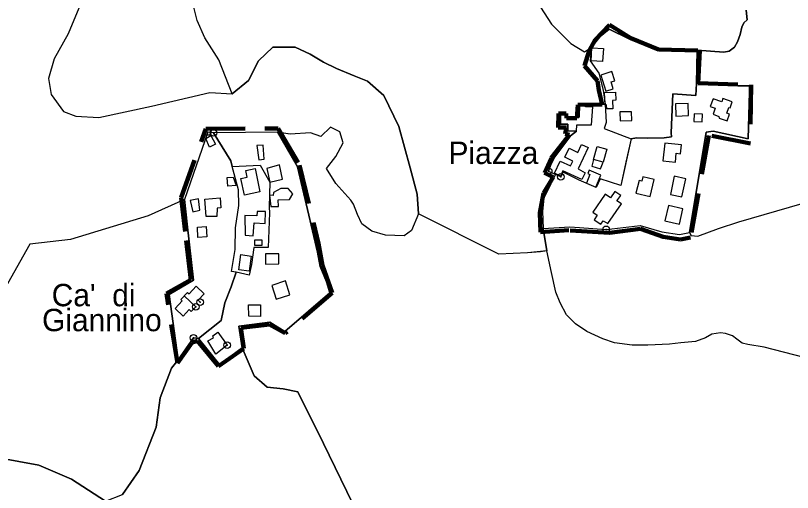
# Model space of a CAD drawing. Extents: x 645880 to 658994, y 884400 to 894744.
# Drawn here: x 655242 to 655833, y 890454 to 890817 of the extents above; entities that cross this region are included whole.
import ezdxf
from ezdxf.enums import TextEntityAlignment as Align

# ---------------------------------------------------------------- set-up
doc = ezdxf.new("R2010")
doc.units = 0
doc.header["$LTSCALE"] = 10
doc.header["$PDMODE"] = 32
doc.header["$PDSIZE"] = 5
doc.linetypes.add('MEDIUM_DASHED', pattern=[4.5, 3, -1.5])
for name, color, linetype, lineweight in [('1', 7, 'Continuous', 25), ('15', 7, 'MEDIUM_DASHED', 100), ('16', 7, 'Continuous', 25), ('17', 7, 'Continuous', 25), ('18', 7, 'Continuous', 25), ('6', 7, 'Continuous', 25), ('7', 7, 'Continuous', 25), ('8', 7, 'Continuous', 25)]:
    doc.layers.add(name, color=color, linetype=linetype, lineweight=lineweight)
doc.layers.add('60', color=7, linetype='Continuous')

msp = doc.modelspace()

# ---------------------------------------------------------------- linework, layer by layer
at = {"layer": '1'}
msp.add_line((655647.79, 890698.77), (655649.57, 890703.78), dxfattribs=at)
for points in [[(655649.57, 890703.78), (655652.57, 890709.54), (655664.32, 890725.65), (655668.89, 890729.13), (655662.28, 890729.46), (655662.45, 890734.52), (655656.71, 890734.52), (655656.76, 890743.16), (655660.15, 890743.1), (655661.16, 890739.83), (655670.97, 890739.81), (655671.21, 890749.71), (655690.79, 890749.71), (655691.6, 890735.82), (655690.08, 890731.27), (655710.46, 890723.26)], [(655710.46, 890723.26), (655702.73, 890687.68), (655702.73, 890687.68), (655686.92, 890692.88), (655683.99, 890686.3)], [(655419.88, 890619.66), (655410.21, 890621.76), (655406.66, 890622.39), (655409.28, 890639.09), (655409.58, 890655.51), (655412.22, 890672.67), (655411.84, 890684.39), (655407.01, 890702.26), (655428.3, 890703.16), (655435.65, 890690.35)], [(655683.99, 890686.3), (655671.13, 890691.84), (655658.88, 890697.92), (655657.03, 890694.32)], [(655435.65, 890690.35), (655435.08, 890671.35), (655435.49, 890667), (655434.49, 890640.6), (655423.6, 890640.6), (655421.67, 890627.77), (655419.88, 890619.66)]]:
    msp.add_lwpolyline(points, dxfattribs=at)
for points in [[(655656.76, 890743.16), (655656.71, 890734.52), (655662.45, 890734.52), (655662.28, 890729.46), (655665.58, 890729.3), (655668.89, 890729.13), (655669.21, 890734), (655680.33, 890733.88), (655681.28, 890747.57), (655675.84, 890747.65), (655675.92, 890749.55), (655671.21, 890749.71), (655670.97, 890739.81), (655661.16, 890739.83), (655660.15, 890743.1)], [(655663.36, 890716.08), (655669.96, 890713), (655672.8, 890719.08), (655677.85, 890716.72), (655670.25, 890700.46), (655675.47, 890697.47), (655673.05, 890692.3), (655658.63, 890699.05), (655656.71, 890694.98), (655652.27, 890697.08), (655656.67, 890706.41), (655664.53, 890702.7), (655666.26, 890706.37), (655660.14, 890709.26)], [(655684.82, 890717.43), (655691.99, 890715.33), (655689.19, 890705.47), (655682.02, 890707.57)], [(655682.02, 890707.57), (655680.64, 890702.48), (655687.34, 890700.47), (655689.19, 890705.47)], [(655413.64, 890693.21), (655418.46, 890694.21), (655417.42, 890699.2), (655424.43, 890700.7), (655428.02, 890682.85), (655416.32, 890680.37)], [(655678.56, 890699.41), (655677.5, 890696.82), (655679.23, 890696.11), (655676.52, 890689.53), (655683.62, 890686.61), (655687.38, 890695.77)], [(655416.72, 890665.06), (655416.93, 890649.94), (655423.1, 890649.57), (655423.78, 890659.29), (655432.27, 890658.95), (655432.33, 890667.91), (655426, 890668.09), (655425.78, 890664.7)], [(655424.04, 890646.15), (655424.04, 890642.48), (655429.89, 890642.48), (655429.89, 890646.15)], [(655413.73, 890635.25), (655421.6, 890634.1), (655419.92, 890622.57), (655412.05, 890623.72)]]:
    msp.add_lwpolyline(points, close=True, dxfattribs=at)
for p in [(655647.79, 890698.77), (655657.03, 890694.32)]:
    msp.add_point(p, dxfattribs=at)
at = {"layer": '15'}
for points in [[(655651.3, 890694.18), (655644.71, 890697.48), (655649.71, 890708.47), (655663.69, 890726.39), (655660.48, 890727.16), (655661.31, 890731.96), (655655.15, 890731.84), (655655.27, 890742.64), (655661.07, 890742.45), (655661.48, 890738.92), (655669.36, 890738.92), (655670.08, 890749.1), (655688.57, 890749.53), (655685.93, 890760.23), (655685.07, 890767.48), (655675.03, 890778.79), (655678.58, 890790.24), (655683.27, 890798.59), (655694.09, 890809.91), (655710.31, 890799.85), (655731.34, 890791.17), (655762.91, 890790.52), (655761.62, 890765.71), (655801.88, 890764.41), (655801.23, 890719.62)], [(655365.45, 890552.49), (655357.01, 890605.61), (655375.74, 890616.11), (655371.19, 890652.68), (655368.31, 890678.68), (655386.93, 890730.93), (655442.05, 890731.2), (655458.32, 890703.36)], [(655801.23, 890719.62), (655769.75, 890725.88), (655755.79, 890648.27)], [(655458.32, 890703.36), (655472.67, 890643.7), (655475.76, 890626.82), (655483.15, 890606.1), (655447.36, 890575.34)], [(655755.79, 890648.27), (655748.21, 890646.63), (655734.79, 890648.8), (655717.66, 890654.75), (655694.13, 890651.68), (655663.05, 890653.74), (655641.7, 890652.31), (655641.12, 890667.08), (655643.99, 890681.99), (655651.3, 890694.18)], [(655447.36, 890575.34), (655435.42, 890582.14), (655413.61, 890579.46), (655416.04, 890563.82)], [(655416.04, 890563.82), (655396.73, 890550.22), (655380.68, 890569.58), (655376.56, 890568.34), (655365.45, 890552.49)]]:
    msp.add_lwpolyline(points, dxfattribs=at)
at = {"layer": '16'}
for points in [[(655241.73, 890961.33), (655257.19, 890954.82), (655267.5, 890950.82), (655278.84, 890941.82), (655285.55, 890927.82), (655270.48, 890913.33), (655263.24, 890906.09), (655251.79, 890895.83), (655262.04, 890891), (655263.85, 890877.72), (655279.52, 890861.43), (655300.63, 890848.76), (655294.25, 890832.09), (655282.39, 890803.09), (655271.56, 890784.08), (655267.44, 890769.08), (655269.5, 890757.08), (655278.78, 890744.07), (655288.06, 890740.57), (655305.59, 890739.57), (655345.8, 890748.08), (655390.13, 890758.58), (655407.04, 890757.59)], [(655407.04, 890757.59), (655396.88, 890783.48), (655386.25, 890800.26), (655380.56, 890813.3), (655376.36, 890829.79), (655372.77, 890846.87), (655374.42, 890869.5), (655379.66, 890877.74), (655397.63, 890890.18), (655409.32, 890897.82), (655411.71, 890906.96), (655408.4, 890909.37), (655401.06, 890915.82), (655395.82, 890921.06), (655385.93, 890929.75), (655380.99, 890940.39), (655375.23, 890951.73)], [(655797.97, 890821.1), (655798.83, 890813.93), (655796.25, 890811.64), (655794.82, 890808.19), (655793.38, 890802.74), (655791.38, 890797), (655789.08, 890792.99), (655785.07, 890790.12), (655781.05, 890789.26), (655760.74, 890790.65), (655760.24, 890765.33), (655791.98, 890763.71)], [(655791.98, 890763.71), (655800.55, 890763.52), (655800.55, 890758.89), (655799.61, 890723.33), (655772.86, 890729.15), (655767.67, 890728.27), (655754.95, 890652.05), (655756.3, 890649.77), (655761.27, 890649.28)], [(655646.5, 890637.96), (655631.75, 890636.44), (655609.85, 890635.63), (655548.75, 890666.18), (655543.59, 890653.67), (655537.99, 890649.56), (655523.59, 890650.1), (655513.34, 890653.12), (655505.81, 890658.55), (655502.49, 890665.79), (655499.48, 890673.64), (655497.39, 890676.63), (655486, 890689.35), (655478.76, 890700.82), (655486, 890709.87), (655491.42, 890720.13), (655489.01, 890728.58), (655481.78, 890732.2), (655474.54, 890724.96), (655466.7, 890727.97), (655451.06, 890726.93), (655441.49, 890728.27), (655456.86, 890701.91)], [(655456.86, 890701.91), (655472.03, 890637.14), (655474.08, 890626.21), (655478.74, 890614.51), (655481.25, 890606.01), (655447.03, 890576.71), (655435.65, 890583.75), (655412.21, 890580.81), (655414.58, 890564.19)], [(655366, 890555.06), (655359.08, 890604.81), (655377.58, 890615.75), (655372.74, 890658.3), (655370.84, 890677.13), (655343.25, 890664.71), (655284.17, 890646.61), (655253.17, 890643.11), (655236.29, 890612.93)], [(655761.27, 890649.28), (655776.89, 890655.05), (655792.34, 890660.05), (655840.64, 890674.02)], [(655842.21, 890557.03), (655811.7, 890564.82), (655799.33, 890566.82), (655795, 890567.8), (655791.04, 890570.99), (655787.54, 890573.35), (655782.3, 890575.12), (655778.58, 890575.63), (655772.04, 890574.64), (655767.23, 890571.96), (655759.42, 890569.01), (655748.42, 890568.03), (655739.8, 890567.12), (655723.12, 890566.21), (655711.25, 890566.21), (655697.99, 890568.01), (655688.91, 890571.17), (655676.81, 890576.59), (655668.2, 890582.46), (655661.45, 890589.46), (655656.56, 890598.49), (655653.31, 890606.61), (655650.07, 890621.67), (655646.5, 890637.96)], [(655414.58, 890564.19), (655397.3, 890551.65), (655381.56, 890571.38), (655377.62, 890571.97), (655366, 890555.06)], [(655583.86, 890382.52), (655572.05, 890388.55), (655552.45, 890394.67), (655536.53, 890403.25), (655521.83, 890415.51), (655498.56, 890446.15), (655476.51, 890491.5), (655456.91, 890530.73), (655445.88, 890533.18), (655433.63, 890534.4), (655423.83, 890542.98), (655414.58, 890564.19)], [(655414.58, 890564.19), (655423.83, 890542.98), (655433.63, 890534.4), (655445.88, 890533.18), (655456.91, 890530.73), (655476.51, 890491.5), (655498.56, 890446.15)], [(655310.73, 890447.52), (655323.57, 890452.71), (655336.37, 890470.85), (655349.17, 890503.93), (655352.37, 890526.34), (655360.9, 890548.75), (655366, 890555.06)], [(655366, 890555.06), (655360.9, 890548.75), (655352.37, 890526.34), (655349.17, 890503.93), (655336.37, 890470.85), (655323.57, 890452.71)], [(655152.23, 890456.28), (655163.35, 890470.47), (655173.64, 890479.1), (655185.87, 890460.18), (655194.49, 890472.42), (655203.39, 890481.88), (655229.25, 890480.49), (655260.12, 890474.93), (655284.74, 890464.35), (655310.73, 890447.52)]]:
    msp.add_lwpolyline(points, dxfattribs=at)
at = {"layer": '17'}
msp.add_line((655647.79, 890698.77), (655653.01, 890696.26), dxfattribs=at)
for points in [[(655641.53, 890637.43), (655631.75, 890636.44), (655609.85, 890635.63), (655548.75, 890666.18), (655547.72, 890681.18), (655542.56, 890701.18), (655533.8, 890732.69), (655522.46, 890756.19), (655510.09, 890767.19), (655499.77, 890771.2), (655486.37, 890776.7), (655476.58, 890781.7), (655466.33, 890787.59), (655454.99, 890793.1), (655437.97, 890793.1), (655427.15, 890782.59), (655419.41, 890767.59), (655407.04, 890757.59), (655396.88, 890783.48), (655386.25, 890800.26), (655380.56, 890813.3), (655376.36, 890829.79)], [(655641.7, 890823.59), (655650.02, 890810.59), (655664.68, 890795.93), (655675.01, 890789.59), (655680.47, 890792.99), (655687.08, 890801.22), (655693.81, 890806.84), (655709.28, 890799.08), (655721.67, 890794.44), (655732.63, 890790.72), (655760.74, 890790.66), (655781.06, 890789.26), (655785.07, 890790.12), (655789.08, 890792.99), (655791.38, 890797.01), (655793.39, 890802.75), (655794.82, 890808.2), (655796.25, 890811.64), (655798.83, 890813.93), (655797.97, 890821.11)], [(655641.7, 890823.59), (655650.02, 890810.59), (655664.68, 890795.93), (655675.01, 890789.59), (655680.47, 890792.99), (655679.34, 890782.76), (655686.08, 890773.27), (655689.34, 890760.2), (655690.79, 890749.71)], [(655690.79, 890749.71), (655671.21, 890749.71), (655670.97, 890739.81), (655661.16, 890739.83), (655660.15, 890743.1), (655656.76, 890743.16), (655656.71, 890734.52), (655662.45, 890734.52), (655662.28, 890729.46), (655668.89, 890729.13), (655664.32, 890725.65), (655652.57, 890709.54), (655649.57, 890703.78), (655647.79, 890698.77)], [(655653.01, 890696.25), (655649.42, 890689.08), (655644.24, 890678.15), (655643.15, 890667.92), (655643.55, 890654.98), (655646.5, 890637.96), (655641.53, 890637.43)]]:
    msp.add_lwpolyline(points, dxfattribs=at)
at = {"layer": '18'}
for points in [[(655241.73, 890961.33), (655257.19, 890954.82), (655267.5, 890950.82), (655278.84, 890941.82), (655285.55, 890927.82), (655270.48, 890913.33), (655263.24, 890906.09), (655251.79, 890895.83), (655262.04, 890891), (655263.85, 890877.72), (655279.52, 890861.43), (655300.63, 890848.76), (655294.25, 890832.09), (655282.39, 890803.09), (655271.56, 890784.08), (655267.44, 890769.08), (655269.5, 890757.08), (655278.78, 890744.07), (655288.06, 890740.57), (655305.59, 890739.57), (655345.8, 890748.08), (655390.13, 890758.58)], [(655390.13, 890758.58), (655407.04, 890757.59), (655419.41, 890767.59), (655427.15, 890782.59), (655437.97, 890793.1), (655454.99, 890793.1), (655466.33, 890787.59), (655476.58, 890781.7), (655486.37, 890776.7), (655499.77, 890771.2), (655510.09, 890767.19), (655522.46, 890756.19), (655533.8, 890732.69), (655542.56, 890701.18), (655547.72, 890681.18), (655548.75, 890666.18), (655543.59, 890653.67), (655537.99, 890649.56), (655523.59, 890650.1), (655513.34, 890653.12), (655505.81, 890658.55), (655502.49, 890665.79), (655499.48, 890673.64), (655497.39, 890676.63), (655486, 890689.35), (655478.76, 890700.82), (655486, 890709.87), (655491.42, 890720.13), (655489.01, 890728.58), (655481.78, 890732.2), (655474.54, 890724.96), (655466.7, 890727.97), (655451.06, 890726.93), (655446.11, 890727.68), (655441.49, 890728.27), (655392.91, 890727.91), (655388.61, 890728.47)], [(655388.61, 890728.47), (655370.84, 890677.13), (655343.25, 890664.71), (655284.17, 890646.61), (655253.17, 890643.11), (655236.29, 890612.93)], [(655761.27, 890649.28), (655776.89, 890655.05), (655792.34, 890660.05), (655840.64, 890674.02)], [(655697.99, 890568.01), (655688.91, 890571.17), (655676.81, 890576.59), (655668.2, 890582.46), (655661.45, 890589.46), (655656.56, 890598.49), (655653.31, 890606.61), (655650.07, 890621.67), (655646.5, 890637.96), (655643.55, 890654.98), (655663.88, 890656.42), (655671.37, 890655.88), (655691.59, 890654.42)], [(655691.59, 890654.42), (655717.46, 890657.36), (655733.95, 890652.58), (655747.37, 890650.41), (655754.95, 890652.05), (655756.3, 890649.77), (655761.27, 890649.28)], [(655842.21, 890557.03), (655811.7, 890564.82), (655799.33, 890566.82), (655795, 890567.8), (655791.04, 890570.99), (655787.54, 890573.35), (655782.3, 890575.12), (655778.58, 890575.63), (655772.04, 890574.64), (655767.23, 890571.96), (655759.42, 890569.01), (655748.42, 890568.03), (655739.8, 890567.12), (655723.12, 890566.21), (655711.25, 890566.21), (655697.99, 890568.01)], [(655226.17, 890309.83), (655244.71, 890308.44), (655250.36, 890315.15), (655256.33, 890332.35), (655262.12, 890339.95), (655270.08, 890341.94), (655283.11, 890339.59), (655294.14, 890337.23), (655298.01, 890338.65), (655291.63, 890352.64), (655287.44, 890365.64), (655287.37, 890380.6), (655281.08, 890400.19), (655287.93, 890413.99), (655290.98, 890427.34), (655297.48, 890443.97), (655310.73, 890447.52), (655284.74, 890464.35), (655260.12, 890474.93), (655229.25, 890480.49)]]:
    msp.add_lwpolyline(points, dxfattribs=at)
for p in [(655388.61, 890728.47), (655691.59, 890654.42)]:
    msp.add_point(p, dxfattribs=at)
at = {"layer": '6'}
msp.add_line((655370.56, 890603.74), (655379.36, 890595.43), dxfattribs=at)
for points in [[(655787.46, 890751.41), (655780.3, 890753.95), (655779.43, 890751.5), (655772.83, 890753.85), (655770.76, 890748.01), (655774.52, 890746.67), (655772.85, 890741.96), (655777.37, 890740.35), (655777.54, 890739.02), (655783.57, 890736.87), (655785.44, 890742.15), (655783.37, 890742.89), (655784.91, 890747.22), (655785.85, 890746.89)], [(655440.53, 890601.3), (655450.99, 890604.71), (655447.57, 890615.17), (655437.11, 890611.76)]]:
    msp.add_lwpolyline(points, close=True, dxfattribs=at)
for points in [[(655379.36, 890595.43), (655375.99, 890591.86), (655374.39, 890593.38), (655369.72, 890588.43), (655363.62, 890594.2), (655369.04, 890599.95), (655367.95, 890600.98), (655373.17, 890606.5), (655374.26, 890605.47), (655379.69, 890611.21)], [(655379.69, 890611.21), (655385.79, 890605.44), (655381.12, 890600.5), (655382.72, 890598.99)]]:
    msp.add_lwpolyline(points, dxfattribs=at)
for p in [(655382.72, 890598.99), (655379.36, 890595.43)]:
    msp.add_point(p, dxfattribs=at)
at = {"layer": '7'}
msp.add_line((655396.24, 890576.1), (655403.21, 890566.31), dxfattribs=at)
for points in [[(655680.69, 890792.47), (655689.46, 890791.93), (655688.85, 890782.09), (655680.08, 890782.63)], [(655687.57, 890771.82), (655691.41, 890759.59), (655696.95, 890761.33), (655695.29, 890766.6), (655698.04, 890767.47), (655695.83, 890774.44)], [(655691.82, 890749.06), (655690.81, 890748.95), (655690.25, 890758.5), (655698.73, 890758.69), (655698.86, 890752.6), (655696.37, 890752.54), (655696.51, 890746.23), (655691.95, 890746.12)], [(655744.22, 890749.93), (655744.5, 890740.64), (655754.14, 890740.93), (655753.86, 890750.22)], [(655701.92, 890743.81), (655702.16, 890737), (655711.02, 890737.23), (655710.86, 890743.79)], [(655758.56, 890742.4), (655758.34, 890736.45), (655764.51, 890736.22), (655764.73, 890742.17)], [(655390.87, 890725.77), (655394.31, 890719.17), (655389.9, 890717.03), (655387, 890723.63)], [(655736.12, 890720.03), (655734.76, 890706.48), (655744.21, 890705.52), (655744.9, 890712.3), (655748.12, 890711.98), (655748.8, 890718.76)], [(655430.61, 890718.4), (655425.88, 890718.31), (655427.34, 890707.39), (655431.3, 890707.82)], [(655442.99, 890703.43), (655433.36, 890700.68), (655435.77, 890690.45), (655445.31, 890692.6)], [(655743.4, 890694.8), (655740.42, 890681.05), (655749.21, 890679.14), (655752.19, 890692.89)], [(655403.31, 890693.8), (655407.88, 890694.22), (655410.09, 890687.79), (655403.84, 890687.39)], [(655719.33, 890694.44), (655718.56, 890691.21), (655716.54, 890691.69), (655714.2, 890681.84), (655724.9, 890679.3), (655728.01, 890692.38)], [(655449.77, 890685.46), (655444.01, 890685.38), (655438.6, 890682.37), (655438.25, 890680.22), (655435.42, 890680.39), (655436.56, 890671.79), (655442.21, 890671.87), (655441.95, 890676.86), (655450.63, 890677.03), (655453.12, 890681.34)], [(655690.91, 890681.31), (655681.32, 890667.49), (655684.66, 890665.17), (655682.31, 890661.79), (655687.39, 890658.26), (655689.3, 890661.01), (655692.73, 890658.79), (655703.21, 890673.87), (655699.78, 890676), (655702.61, 890680.08), (655698.85, 890682.77), (655698.18, 890683.23), (655694.96, 890678.53)], [(655381.42, 890677.56), (655375.2, 890676.47), (655377.25, 890667.88), (655382.53, 890669)], [(655386.29, 890677.44), (655397.87, 890678.51), (655398.45, 890670.9), (655395.64, 890670.44), (655395.49, 890664.2), (655387.21, 890664.3)], [(655738.84, 890672.52), (655736.14, 890660.87), (655747.26, 890658.29), (655749.96, 890669.94)], [(655380.57, 890656.17), (655387.21, 890656.58), (655387.67, 890648.66), (655380.98, 890648.25)], [(655442.49, 890635.68), (655432.47, 890635.68), (655432.38, 890628), (655442.52, 890628.18)], [(655419.61, 890597.12), (655428.61, 890597.12), (655428.67, 890588.06), (655419.78, 890588.28)]]:
    msp.add_lwpolyline(points, close=True, dxfattribs=at)
msp.add_lwpolyline([(655403.21, 890566.31), (655394.51, 890559.44), (655388.51, 890569.5), (655392.89, 890571.77), (655392.24, 890573.4), (655396.24, 890576.1)], dxfattribs=at)
msp.add_point((655403.21, 890566.31), dxfattribs=at)
at = {"layer": '8'}
for points in [[(655760.74, 890790.66), (655732.63, 890790.72), (655721.67, 890794.44), (655709.28, 890799.08), (655707.66, 890799.98), (655706.87, 890800.29), (655693.81, 890806.84), (655687.08, 890801.22), (655680.47, 890792.99), (655679.34, 890782.76), (655686.08, 890773.27), (655689.34, 890760.2), (655690.79, 890749.71), (655691.6, 890735.82)], [(655710.46, 890723.26), (655714.74, 890724.03), (655722.92, 890723.72), (655735.74, 890723.97), (655741.29, 890724.86), (655740.98, 890727.97), (655742.36, 890757.53), (655759.74, 890756.34), (655760.24, 890765.34), (655760.74, 890790.66)], [(655754.95, 890652.05), (655767.67, 890728.28), (655772.86, 890729.16), (655799.61, 890723.34), (655800.55, 890758.9), (655800.55, 890763.53), (655791.98, 890763.72), (655760.24, 890765.34), (655759.74, 890756.34), (655742.36, 890757.53)], [(655742.36, 890757.53), (655740.98, 890727.97), (655741.29, 890724.86)], [(655691.6, 890735.82), (655690.08, 890731.27), (655710.46, 890723.26)], [(655392.91, 890727.91), (655388.61, 890728.47), (655370.84, 890677.13), (655372.74, 890658.3)], [(655406.38, 890610.67), (655410.21, 890621.76), (655406.66, 890622.39), (655409.28, 890639.09), (655409.58, 890655.51), (655412.22, 890672.67), (655411.84, 890684.39), (655407.01, 890702.26), (655406.02, 890706.44), (655392.91, 890727.91)], [(655741.29, 890724.86), (655735.74, 890723.97), (655722.92, 890723.72), (655714.74, 890724.03), (655710.46, 890723.26)], [(655710.46, 890723.26), (655706.6, 890705.47), (655702.73, 890687.68), (655686.92, 890692.88), (655683.99, 890686.3), (655671.13, 890691.84), (655658.88, 890697.92), (655657.03, 890694.31), (655653.01, 890696.25), (655649.42, 890689.08), (655644.24, 890678.15), (655643.15, 890667.92), (655643.55, 890654.98), (655663.88, 890656.42), (655671.37, 890655.88), (655691.59, 890654.42)], [(655372.74, 890658.3), (655377.58, 890615.75), (655359.08, 890604.81), (655366, 890555.06), (655377.62, 890571.97), (655381.56, 890571.38), (655398.64, 890584.96), (655401.56, 890598.55), (655406.38, 890610.67)], [(655691.59, 890654.42), (655717.46, 890657.36), (655733.95, 890652.58), (655747.37, 890650.41), (655754.95, 890652.05)]]:
    msp.add_lwpolyline(points, dxfattribs=at)
msp.add_lwpolyline([(655381.56, 890571.38), (655397.3, 890551.65), (655414.58, 890564.19), (655412.21, 890580.81), (655435.65, 890583.75), (655447.03, 890576.71), (655481.25, 890606.01), (655478.74, 890614.51), (655474.08, 890626.21), (655472.03, 890637.14), (655456.86, 890701.91), (655441.49, 890728.27), (655392.91, 890727.91), (655406.02, 890706.44), (655407.01, 890702.26), (655428.3, 890703.16), (655435.65, 890690.35), (655435.65, 890690.35), (655435.08, 890671.35), (655435.49, 890667), (655434.49, 890640.6), (655423.6, 890640.6), (655421.67, 890627.77), (655419.88, 890619.66), (655410.21, 890621.76), (655406.38, 890610.67), (655401.56, 890598.55), (655398.64, 890584.96)], close=True, dxfattribs=at)
for p in [(655392.91, 890727.91), (655377.62, 890571.97)]:
    msp.add_point(p, dxfattribs=at)

# ---------------------------------------------------------------- texts
at = {"layer": '60'}
for s, p in [('Piazza', (655605.78, 890704.14)), ("Ca'  di  ", (655307.97, 890595.92)), ('Giannino', (655307.97, 890576.93))]:
    msp.add_text(s, height=17, dxfattribs=at).set_placement(p, align=Align.CENTER)

doc.saveas('drawing.dxf')
